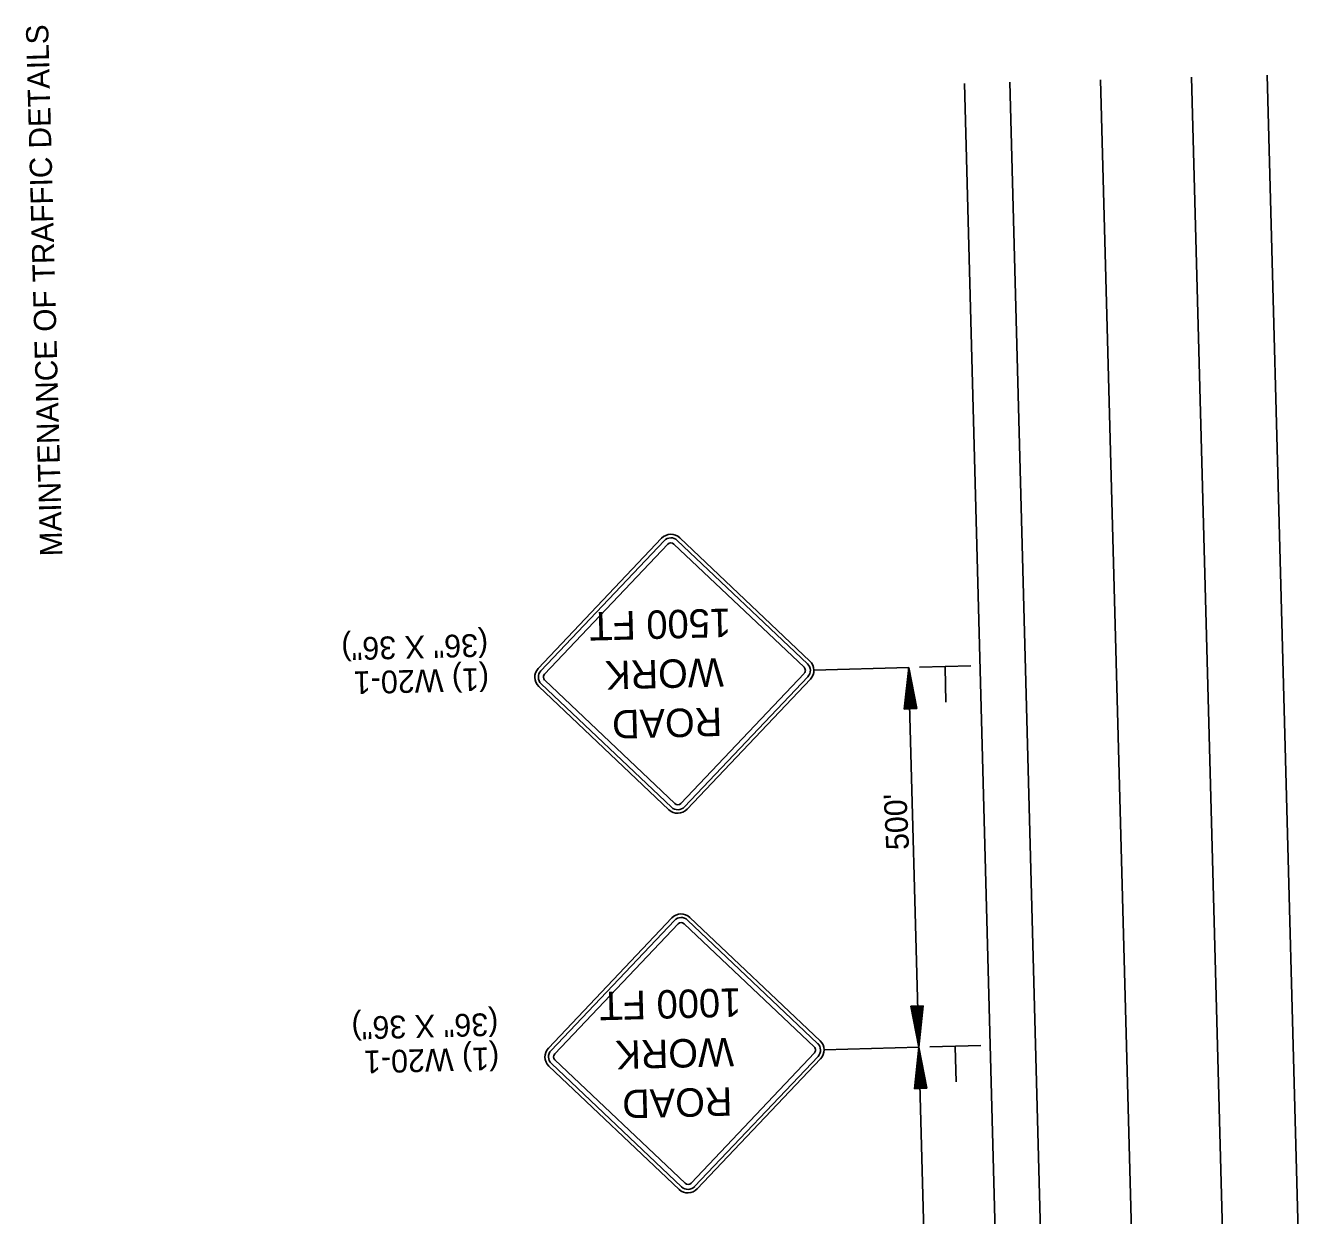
# Model space of a CAD drawing. Extents: x 1930579 to 1931593, y 596452 to 598537.
# Drawn here: x 1930608.2 to 1930946.9, y 598217.2 to 598530.8 of the extents above; entities that cross this region are included whole.
import ezdxf

# ---------------------------------------------------------------- set-up
doc = ezdxf.new("R2010")
doc.units = 0
for name, color, linetype in [('P_TC_Signs_Temporary', 7, 'Continuous'), ('R_Annotation', 7, 'Continuous'), ('R_Border', 7, 'Continuous'), ('R_Draft', 7, 'Continuous')]:
    doc.layers.add(name, color=color, linetype=linetype)

msp = doc.modelspace()

# ---------------------------------------------------------------- linework, layer by layer
at = {"layer": 'P_TC_Signs_Temporary'}
for p, q in [((1930743.22, 598361.36), (1930775.72, 598395.65)), ((1930743.9, 598360.71), (1930776.4, 598395.01)), ((1930744.85, 598359.81), (1930777.36, 598394.1)), ((1930778.95, 598394.15), (1930813.24, 598361.64)), ((1930779.85, 598395.1), (1930814.15, 598362.6)), ((1930780.49, 598395.78), (1930814.79, 598363.28)), ((1930813.29, 598360.05), (1930780.78, 598325.76)), ((1930777.64, 598324.08), (1930743.35, 598356.59)), ((1930778.29, 598324.76), (1930743.99, 598357.27)), ((1930779.19, 598325.72), (1930744.9, 598358.22)), ((1930814.24, 598359.15), (1930781.74, 598324.86)), ((1930814.92, 598358.51), (1930782.42, 598324.21)), ((1930745.91, 598261.27), (1930778.41, 598295.57)), ((1930783.18, 598295.69), (1930817.48, 598263.19)), ((1930746.59, 598260.63), (1930779.09, 598294.92)), ((1930747.54, 598259.72), (1930780.05, 598294.02)), ((1930781.64, 598294.06), (1930815.93, 598261.56)), ((1930782.54, 598295.01), (1930816.83, 598262.51)), ((1930781.88, 598225.63), (1930747.59, 598258.13)), ((1930815.97, 598259.97), (1930783.47, 598225.67)), ((1930816.93, 598259.07), (1930784.42, 598224.77)), ((1930817.61, 598258.42), (1930785.11, 598224.13)), ((1930780.33, 598224), (1930746.04, 598256.5)), ((1930780.98, 598224.68), (1930746.68, 598257.18))]:
    msp.add_line(p, q, dxfattribs=at)
for centre, radius, start, end in [((1930778.17, 598393.33), 3.38, 46.5377, 136.5377), ((1930778.17, 598393.33), 2.44, 46.5377, 136.5377), ((1930778.17, 598393.33), 1.13, 46.5377, 136.5377), ((1930812.47, 598360.83), 3.38, 316.5377, 46.5377), ((1930745.67, 598359.04), 3.38, 136.5377, 226.5377), ((1930745.67, 598359.04), 2.44, 136.5377, 226.5377), ((1930745.67, 598359.04), 1.12, 136.5377, 226.5377), ((1930812.47, 598360.83), 1.12, 316.5377, 46.5377), ((1930812.47, 598360.83), 2.44, 316.5377, 46.5377), ((1930779.97, 598326.53), 1.13, 226.5377, 316.5377), ((1930779.97, 598326.53), 3.37, 226.5377, 316.5377), ((1930779.97, 598326.53), 2.44, 226.5377, 316.5377), ((1930780.86, 598293.24), 3.38, 46.5377, 136.5377), ((1930780.86, 598293.24), 2.44, 46.5377, 136.5377), ((1930780.86, 598293.24), 1.13, 46.5377, 136.5377), ((1930815.16, 598260.74), 1.12, 316.5377, 46.5377), ((1930815.16, 598260.74), 2.44, 316.5377, 46.5377), ((1930815.16, 598260.74), 3.38, 316.5377, 46.5377), ((1930748.36, 598258.95), 3.38, 136.5377, 226.5377), ((1930748.36, 598258.95), 2.44, 136.5377, 226.5377), ((1930748.36, 598258.95), 1.12, 136.5377, 226.5377), ((1930782.66, 598226.45), 3.37, 226.5377, 316.5377), ((1930782.66, 598226.45), 2.44, 226.5377, 316.5377), ((1930782.66, 598226.45), 1.13, 226.5377, 316.5377)]:
    msp.add_arc(centre, radius, start, end, dxfattribs=at)
at = {"layer": 'R_Draft'}
for p, q in [((1930855.5, 598515.57), (1930867.14, 598081.72)), ((1930867.46, 598515.89), (1930879.11, 598082.04)), ((1930891.39, 598516.53), (1930903.04, 598082.68)), ((1930915.32, 598517.18), (1930926.97, 598083.32)), ((1930935.26, 598517.71), (1930946.91, 598083.86)), ((1930815.84, 598360.92), (1930840.84, 598361.59)), ((1930839.67, 598350.65), (1930840.84, 598361.59)), ((1930839.94, 598350.66), (1930840.92, 598359.77)), ((1930843.53, 598261.5), (1930840.81, 598361.47)), ((1930842.94, 598350.79), (1930840.84, 598361.59)), ((1930842.66, 598350.78), (1930840.92, 598359.77)), ((1930843.7, 598361.67), (1930857.16, 598362.03)), ((1930850.41, 598361.65), (1930850.65, 598352.47)), ((1930840.22, 598350.67), (1930840.99, 598357.91)), ((1930842.38, 598350.76), (1930840.99, 598357.91)), ((1930840.49, 598350.69), (1930841.07, 598356.09)), ((1930840.77, 598350.7), (1930841.15, 598354.25)), ((1930842.11, 598350.75), (1930841.07, 598356.09)), ((1930841.83, 598350.74), (1930841.15, 598354.25)), ((1930839.67, 598350.65), (1930842.94, 598350.79)), ((1930841.05, 598350.71), (1930841.23, 598352.43)), ((1930841.56, 598350.73), (1930841.23, 598352.43)), ((1930844.68, 598272.44), (1930841.42, 598272.3)), ((1930841.42, 598272.3), (1930843.52, 598261.5)), ((1930841.69, 598272.32), (1930843.44, 598263.32)), ((1930841.98, 598272.33), (1930843.36, 598265.19)), ((1930842.24, 598272.34), (1930843.28, 598267)), ((1930842.52, 598272.35), (1930843.21, 598268.84)), ((1930842.8, 598272.36), (1930843.13, 598270.65)), ((1930843.31, 598272.38), (1930843.13, 598270.65)), ((1930843.58, 598272.39), (1930843.21, 598268.84)), ((1930843.86, 598272.41), (1930843.28, 598267)), ((1930844.14, 598272.42), (1930843.36, 598265.19)), ((1930844.41, 598272.43), (1930843.44, 598263.32)), ((1930844.68, 598272.44), (1930843.52, 598261.5)), ((1930818.53, 598260.83), (1930843.52, 598261.5)), ((1930842.36, 598250.56), (1930843.52, 598261.5)), ((1930846.21, 598161.54), (1930843.52, 598261.5)), ((1930845.62, 598250.7), (1930843.52, 598261.5)), ((1930846.39, 598261.58), (1930859.85, 598261.94)), ((1930853.09, 598261.57), (1930853.34, 598252.38)), ((1930842.63, 598250.58), (1930843.6, 598259.69)), ((1930845.35, 598250.69), (1930843.6, 598259.69)), ((1930842.91, 598250.59), (1930843.68, 598257.82)), ((1930843.18, 598250.6), (1930843.76, 598256.01)), ((1930845.07, 598250.68), (1930843.68, 598257.82)), ((1930844.8, 598250.67), (1930843.76, 598256.01)), ((1930843.46, 598250.61), (1930843.84, 598254.16)), ((1930843.73, 598250.62), (1930843.92, 598252.35)), ((1930844.52, 598250.65), (1930843.84, 598254.16)), ((1930844.24, 598250.64), (1930843.92, 598252.35)), ((1930842.36, 598250.56), (1930845.62, 598250.7))]:
    msp.add_line(p, q, dxfattribs=at)

# ---------------------------------------------------------------- texts
at = {"layer": 'P_TC_Signs_Temporary'}
for s, p in [('1500 FT', (1930793.9, 598377.17)), ('WORK', (1930791.95, 598364.09)), (' ROAD ', (1930794.33, 598351.13)), ('1000 FT', (1930796.59, 598277.08)), ('WORK', (1930794.64, 598264)), (' ROAD ', (1930797.02, 598251.04))]:
    msp.add_text(s, height=7.5, rotation=181.5377, dxfattribs=at).set_placement(p)
at = {"layer": 'R_Annotation'}
for s, p in [('(36" X 36")', (1930729.94, 598370.49)), ('(1) W20-1', (1930730.18, 598361.5)), ('(36" X 36")', (1930732.62, 598270.53)), ('(1) W20-1', (1930732.86, 598261.53))]:
    msp.add_text(s, height=6, rotation=181.5377, dxfattribs=at).set_placement(p)
at = {"layer": 'R_Border'}
msp.add_text('MAINTENANCE OF TRAFFIC DETAILS', height=5.862, rotation=91.5377, dxfattribs=at).set_placement((1930617.82, 598390.98))
at = {"layer": 'R_Draft'}
msp.add_text("500'", height=6, rotation=92.7681, dxfattribs=at).set_placement((1930840.93, 598313.61))

doc.saveas('drawing.dxf')
